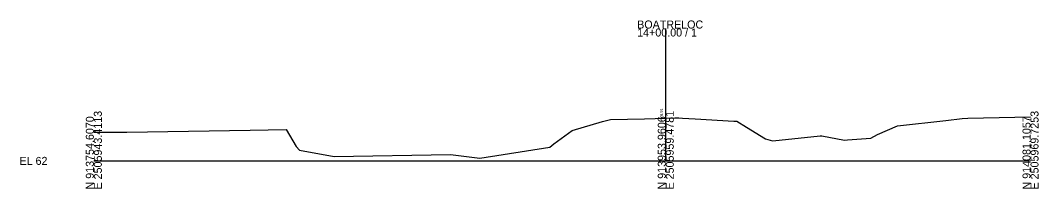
# Model space of a CAD drawing. Extents: x -26 to 403, y -10 to 2549.
# Drawn here: x -25.7 to 330.4, y 2490.3 to 2549.1 of the extents above; entities that cross this region are included whole.
import ezdxf

# ---------------------------------------------------------------- set-up
doc = ezdxf.new("R2010")
doc.units = 0
for name, color, linetype in [('RD_GPK_XS_Cell', 7, 'Continuous'), ('RD_XS_ExGround', 7, 'Continuous'), ('RD_XS_TX_Elev_EX', 7, 'Continuous')]:
    doc.layers.add(name, color=color, linetype=linetype)

msp = doc.modelspace()

# ---------------------------------------------------------------- linework, layer by layer
at = {"layer": 'RD_GPK_XS_Cell'}
for p, q in [((200, 2500), (200, 2546.28)), ((0, 2500), (200, 2500)), ((200, 2500), (327.56, 2500))]:
    msp.add_line(p, q, dxfattribs=at)
at = {"layer": 'RD_XS_ExGround'}
for p, q in [((177.93, 2513.77), (180.7, 2514.51)), ((180.7, 2514.51), (192.53, 2514.71)), ((192.53, 2514.71), (200, 2514.91)), ((200, 2514.91), (203.22, 2515)), ((203.22, 2515), (204.58, 2515.04)), ((204.58, 2515.04), (205.85, 2514.97)), ((205.85, 2514.97), (210.23, 2514.75)), ((210.23, 2514.75), (223.81, 2513.94)), ((281.03, 2512.26), (297.96, 2514.18)), ((297.96, 2514.18), (303.66, 2514.81)), ((303.66, 2514.81), (305.62, 2514.9)), ((305.62, 2514.9), (327.56, 2515.43)), ((11.54, 2510.04), (54.7, 2510.8)), ((54.7, 2510.8), (67.22, 2511)), ((67.22, 2511), (70.8, 2505.08)), ((160.91, 2505.94), (167.3, 2510.6)), ((167.3, 2510.6), (177.93, 2513.77)), ((223.81, 2513.94), (224.81, 2513.85)), ((224.81, 2513.85), (228.19, 2511.79)), ((228.19, 2511.79), (234.9, 2507.73)), ((274.09, 2509.23), (281.03, 2512.26)), ((0, 2510.03), (3.64, 2510.03)), ((3.64, 2510.03), (11.54, 2510.04)), ((234.9, 2507.73), (236.47, 2507.25)), ((236.47, 2507.25), (237.41, 2506.96)), ((237.41, 2506.96), (254.04, 2508.8)), ((254.04, 2508.8), (254.58, 2508.79)), ((254.58, 2508.79), (262.51, 2507.29)), ((262.51, 2507.29), (263.55, 2507.32)), ((263.55, 2507.32), (271.69, 2508)), ((271.69, 2508), (274.09, 2509.23)), ((70.8, 2505.08), (71.96, 2503.81)), ((71.96, 2503.81), (84, 2501.54)), ((135.01, 2501.01), (159.45, 2504.76)), ((159.45, 2504.76), (160.91, 2505.94)), ((84, 2501.54), (124.74, 2502.21)), ((124.74, 2502.21), (135.01, 2501.01))]:
    msp.add_line(p, q, dxfattribs=at)

# ---------------------------------------------------------------- texts
at = {"layer": 'RD_GPK_XS_Cell'}
for s, p in [('14+00.00 / 1', (190, 2543.48)), ('BOATRELOC', (190, 2546.28)), ('EL 62', (-26, 2498.6))]:
    msp.add_text(s, height=2.8, dxfattribs=at).set_placement(p)
for s, p in [('N 913754.6070', (0, 2490)), ('E 2505943.4113', (2.8, 2490)), ('N 913953.9606', (200, 2490)), ('E 2505959.4781', (202.8, 2490)), ('N 914081.1057', (327.56, 2490)), ('E 2505969.7253', (330.36, 2490))]:
    msp.add_text(s, height=2.8, rotation=90, dxfattribs=at).set_placement(p)
at = {"layer": 'RD_XS_TX_Elev_EX'}
msp.add_text('76.91', height=1, rotation=90, dxfattribs=at).set_placement((199, 2514.91))

doc.saveas('drawing.dxf')
